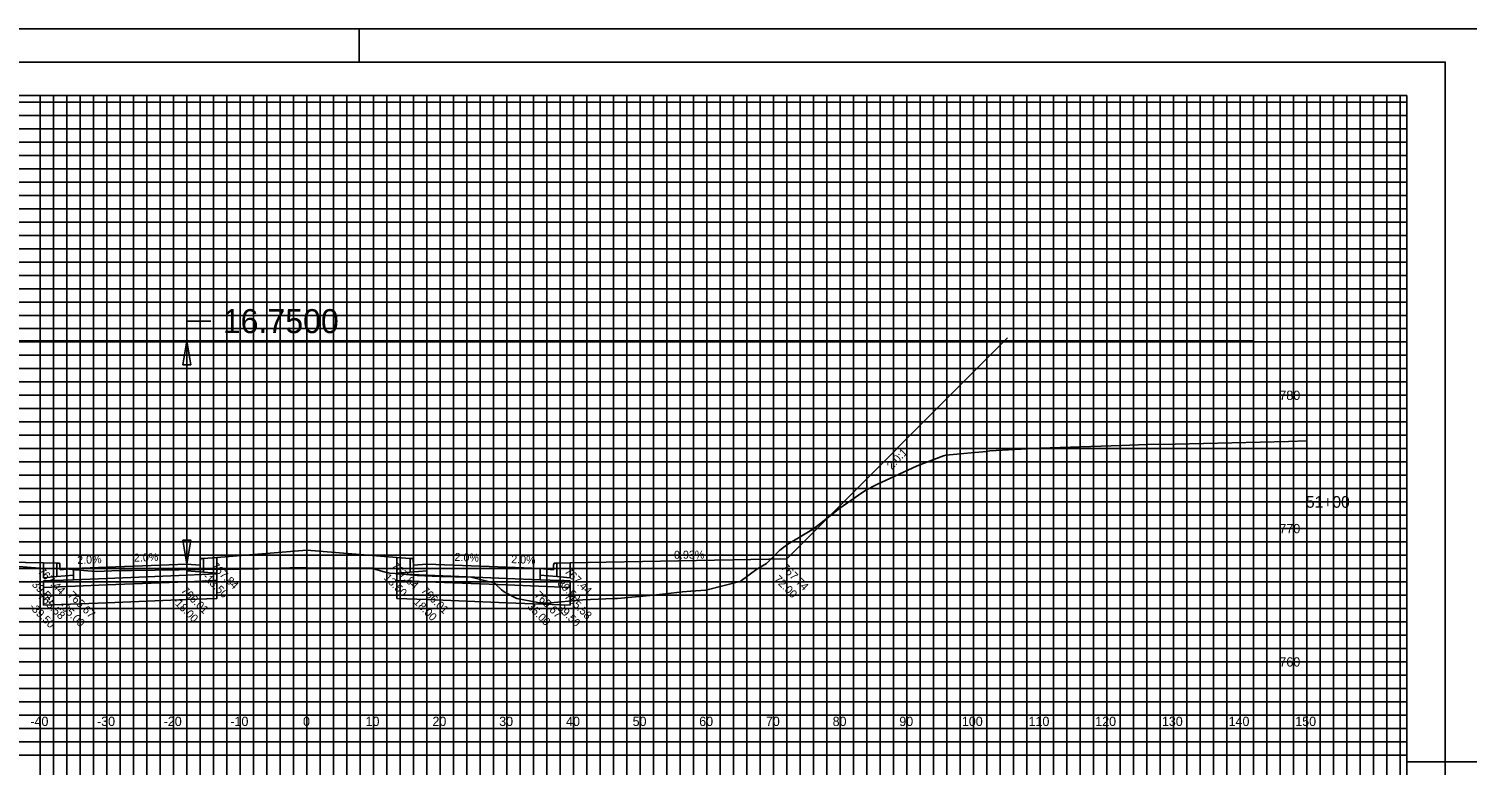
# Model space of a CAD drawing. Extents: x 578243 to 601557, y 174899 to 175559.
# Drawn here: x 600998.1 to 601213.9, y 175448.3 to 175558.8 of the extents above; entities that cross this region are included whole.
import ezdxf

# ---------------------------------------------------------------- set-up
doc = ezdxf.new("R2010")
doc.units = 0
for name, color, linetype in [('E_PROF_Grid', 7, 'Continuous'), ('E_PROF_GridMin', 7, 'Continuous'), ('P_CRDR_Label', 7, 'Continuous'), ('P_CRDR_Link', 7, 'Continuous'), ('P_E_XS_Ground', 7, 'Continuous'), ('P_RW_SlopeIntercepts', 7, 'Continuous'), ('P_XS_Text', 7, 'Continuous'), ('PLT_Sheet_Border', 7, 'Continuous'), ('PLT_Sheet_Info', 7, 'Continuous')]:
    doc.layers.add(name, color=color, linetype=linetype)

msp = doc.modelspace()

# ---------------------------------------------------------------- linework, layer by layer
at = {"layer": 'E_PROF_Grid'}
for p, q in [((600999.84, 175353.8), (600999.84, 175548.8)), ((601009.84, 175353.8), (601009.84, 175548.8)), ((601019.84, 175353.8), (601019.84, 175548.8)), ((601029.84, 175353.8), (601029.84, 175548.8)), ((601039.84, 175353.8), (601039.84, 175548.8)), ((601049.84, 175353.8), (601049.84, 175548.8)), ((601059.84, 175353.8), (601059.84, 175548.8)), ((601069.84, 175353.8), (601069.84, 175548.8)), ((601079.84, 175353.8), (601079.84, 175548.8)), ((601089.84, 175353.8), (601089.84, 175548.8)), ((601099.84, 175353.8), (601099.84, 175548.8)), ((601109.84, 175353.8), (601109.84, 175548.8)), ((601119.84, 175353.8), (601119.84, 175548.8)), ((601129.84, 175353.8), (601129.84, 175548.8)), ((601139.84, 175353.8), (601139.84, 175548.8)), ((601149.84, 175353.8), (601149.84, 175548.8)), ((601159.84, 175353.8), (601159.84, 175548.8)), ((601169.84, 175353.8), (601169.84, 175548.8)), ((601179.84, 175353.8), (601179.84, 175548.8)), ((601189.84, 175353.8), (601189.84, 175548.8)), ((601199.84, 175353.8), (601199.84, 175548.8)), ((600889.84, 175543.8), (601204.84, 175543.8)), ((600889.84, 175533.8), (601204.84, 175533.8)), ((600889.84, 175523.8), (601204.84, 175523.8)), ((600889.84, 175513.8), (601204.84, 175513.8)), ((600889.84, 175503.8), (601204.84, 175503.8)), ((600889.84, 175493.8), (601204.84, 175493.8)), ((600889.84, 175483.8), (601204.84, 175483.8)), ((600889.84, 175473.8), (601204.84, 175473.8)), ((600889.84, 175463.8), (601204.84, 175463.8)), ((600889.84, 175453.8), (601204.84, 175453.8))]:
    msp.add_line(p, q, dxfattribs=at)
at = {"layer": 'E_PROF_GridMin'}
for p, q in [((601001.84, 175353.8), (601001.84, 175548.8)), ((601003.84, 175353.8), (601003.84, 175548.8)), ((601005.84, 175353.8), (601005.84, 175548.8)), ((601007.84, 175353.8), (601007.84, 175548.8)), ((601011.84, 175353.8), (601011.84, 175548.8)), ((601013.84, 175353.8), (601013.84, 175548.8)), ((601015.84, 175353.8), (601015.84, 175548.8)), ((601017.84, 175353.8), (601017.84, 175548.8)), ((601021.84, 175353.8), (601021.84, 175548.8)), ((601023.84, 175353.8), (601023.84, 175548.8)), ((601025.84, 175353.8), (601025.84, 175548.8)), ((601027.84, 175353.8), (601027.84, 175548.8)), ((601031.84, 175353.8), (601031.84, 175548.8)), ((601033.84, 175353.8), (601033.84, 175548.8)), ((601035.84, 175353.8), (601035.84, 175548.8)), ((601037.84, 175353.8), (601037.84, 175548.8)), ((601041.84, 175353.8), (601041.84, 175548.8)), ((601043.84, 175353.8), (601043.84, 175548.8)), ((601045.84, 175353.8), (601045.84, 175548.8)), ((601047.84, 175353.8), (601047.84, 175548.8)), ((601051.84, 175353.8), (601051.84, 175548.8)), ((601053.84, 175353.8), (601053.84, 175548.8)), ((601055.84, 175353.8), (601055.84, 175548.8)), ((601057.84, 175353.8), (601057.84, 175548.8)), ((601061.84, 175353.8), (601061.84, 175548.8)), ((601063.84, 175353.8), (601063.84, 175548.8)), ((601065.84, 175353.8), (601065.84, 175548.8)), ((601067.84, 175353.8), (601067.84, 175548.8)), ((601071.84, 175353.8), (601071.84, 175548.8)), ((601073.84, 175353.8), (601073.84, 175548.8)), ((601075.84, 175353.8), (601075.84, 175548.8)), ((601077.84, 175353.8), (601077.84, 175548.8)), ((601081.84, 175353.8), (601081.84, 175548.8)), ((601083.84, 175353.8), (601083.84, 175548.8)), ((601085.84, 175353.8), (601085.84, 175548.8)), ((601087.84, 175353.8), (601087.84, 175548.8)), ((601091.84, 175353.8), (601091.84, 175548.8)), ((601093.84, 175353.8), (601093.84, 175548.8)), ((601095.84, 175353.8), (601095.84, 175548.8)), ((601097.84, 175353.8), (601097.84, 175548.8)), ((601101.84, 175353.8), (601101.84, 175548.8)), ((601103.84, 175353.8), (601103.84, 175548.8)), ((601105.84, 175353.8), (601105.84, 175548.8)), ((601107.84, 175353.8), (601107.84, 175548.8)), ((601111.84, 175353.8), (601111.84, 175548.8)), ((601113.84, 175353.8), (601113.84, 175548.8)), ((601115.84, 175353.8), (601115.84, 175548.8)), ((601117.84, 175353.8), (601117.84, 175548.8)), ((601121.84, 175353.8), (601121.84, 175548.8)), ((601123.84, 175353.8), (601123.84, 175548.8)), ((601125.84, 175353.8), (601125.84, 175548.8)), ((601127.84, 175353.8), (601127.84, 175548.8)), ((601131.84, 175353.8), (601131.84, 175548.8)), ((601133.84, 175353.8), (601133.84, 175548.8)), ((601135.84, 175353.8), (601135.84, 175548.8)), ((601137.84, 175353.8), (601137.84, 175548.8)), ((601141.84, 175353.8), (601141.84, 175548.8)), ((601143.84, 175353.8), (601143.84, 175548.8)), ((601145.84, 175353.8), (601145.84, 175548.8)), ((601147.84, 175353.8), (601147.84, 175548.8)), ((601151.84, 175353.8), (601151.84, 175548.8)), ((601153.84, 175353.8), (601153.84, 175548.8)), ((601155.84, 175353.8), (601155.84, 175548.8)), ((601157.84, 175353.8), (601157.84, 175548.8)), ((601161.84, 175353.8), (601161.84, 175548.8)), ((601163.84, 175353.8), (601163.84, 175548.8)), ((601165.84, 175353.8), (601165.84, 175548.8)), ((601167.84, 175353.8), (601167.84, 175548.8)), ((601171.84, 175353.8), (601171.84, 175548.8)), ((601173.84, 175353.8), (601173.84, 175548.8)), ((601175.84, 175353.8), (601175.84, 175548.8)), ((601177.84, 175353.8), (601177.84, 175548.8)), ((601181.84, 175353.8), (601181.84, 175548.8)), ((601183.84, 175353.8), (601183.84, 175548.8)), ((601185.84, 175353.8), (601185.84, 175548.8)), ((601187.84, 175353.8), (601187.84, 175548.8)), ((601191.84, 175353.8), (601191.84, 175548.8)), ((601193.84, 175353.8), (601193.84, 175548.8)), ((601195.84, 175353.8), (601195.84, 175548.8)), ((601197.84, 175353.8), (601197.84, 175548.8)), ((601201.84, 175353.8), (601201.84, 175548.8)), ((601203.84, 175353.8), (601203.84, 175548.8)), ((600889.84, 175547.8), (601204.84, 175547.8)), ((600889.84, 175545.8), (601204.84, 175545.8)), ((600889.84, 175541.8), (601204.84, 175541.8)), ((600889.84, 175539.8), (601204.84, 175539.8)), ((600889.84, 175537.8), (601204.84, 175537.8)), ((600889.84, 175535.8), (601204.84, 175535.8)), ((600889.84, 175531.8), (601204.84, 175531.8)), ((600889.84, 175529.8), (601204.84, 175529.8)), ((600889.84, 175527.8), (601204.84, 175527.8)), ((600889.84, 175525.8), (601204.84, 175525.8)), ((600889.84, 175521.8), (601204.84, 175521.8)), ((600889.84, 175519.8), (601204.84, 175519.8)), ((600889.84, 175517.8), (601204.84, 175517.8)), ((600889.84, 175515.8), (601204.84, 175515.8)), ((600889.84, 175511.8), (601204.84, 175511.8)), ((600889.84, 175509.8), (601204.84, 175509.8)), ((600889.84, 175507.8), (601204.84, 175507.8)), ((600889.84, 175505.8), (601204.84, 175505.8)), ((600889.84, 175501.8), (601204.84, 175501.8)), ((600889.84, 175499.8), (601204.84, 175499.8)), ((600889.84, 175497.8), (601204.84, 175497.8)), ((600889.84, 175495.8), (601204.84, 175495.8)), ((600889.84, 175491.8), (601204.84, 175491.8)), ((600889.84, 175489.8), (601204.84, 175489.8)), ((600889.84, 175487.8), (601204.84, 175487.8)), ((600889.84, 175485.8), (601204.84, 175485.8)), ((600889.84, 175481.8), (601204.84, 175481.8)), ((600889.84, 175479.8), (601204.84, 175479.8)), ((600889.84, 175477.8), (601204.84, 175477.8)), ((600889.84, 175475.8), (601204.84, 175475.8)), ((600889.84, 175471.8), (601204.84, 175471.8)), ((600889.84, 175469.8), (601204.84, 175469.8)), ((600889.84, 175467.8), (601204.84, 175467.8)), ((600889.84, 175465.8), (601204.84, 175465.8)), ((600889.84, 175461.8), (601204.84, 175461.8)), ((600889.84, 175459.8), (601204.84, 175459.8)), ((600889.84, 175457.8), (601204.84, 175457.8)), ((600889.84, 175455.8), (601204.84, 175455.8)), ((600889.84, 175451.8), (601204.84, 175451.8)), ((600889.84, 175449.8), (601204.84, 175449.8))]:
    msp.add_line(p, q, dxfattribs=at)
at = {"layer": 'P_CRDR_Link'}
msp.add_line((601144.95, 175512.4), (601111.84, 175479.28), dxfattribs=at)
for points in [[(601026.34, 175479.48), (601039.84, 175480.56)], [(601026.34, 175479.48), (601039.84, 175480.56)], [(601039.84, 175480.56), (601026.34, 175479.48)], [(601039.84, 175480.56), (601053.34, 175479.48)], [(601039.84, 175480.56), (601053.34, 175479.48)], [(601053.34, 175479.48), (601039.84, 175480.56)], [(601000.34, 175478.68), (600967.84, 175479.28)], [(601000.34, 175478.68), (600967.84, 175479.28)], [(601002.34, 175478.64), (601000.34, 175478.68)], [(601000.34, 175478.68), (601000.34, 175476.44)], [(601000.34, 175478.68), (601000.34, 175476.44)], [(601000.34, 175478.68), (601000.34, 175476.44)], [(601002.66, 175478.64), (601002.34, 175478.64)], [(601002.66, 175478.64), (601002.34, 175478.64)], [(601002.34, 175478.64), (601002.34, 175476.6)], [(601002.34, 175476.6), (601002.34, 175478.64)], [(601002.74, 175478.6), (601002.66, 175478.64)], [(601002.74, 175478.6), (601002.66, 175478.64)], [(601002.8, 175478.48), (601002.74, 175478.6)], [(601002.8, 175478.48), (601002.74, 175478.6)], [(601002.82, 175478.32), (601002.8, 175478.48)], [(601002.82, 175478.32), (601002.8, 175478.48)], [(601002.84, 175477.64), (601002.82, 175478.32)], [(601002.84, 175477.64), (601002.82, 175478.32)], [(601004.84, 175477.8), (601002.84, 175477.64)], [(601004.84, 175477.8), (601002.84, 175477.64)], [(601009.84, 175478), (601004.84, 175477.8)], [(601004.84, 175477.8), (601004.84, 175476.14)], [(601004.84, 175476.8), (601004.84, 175477.8)], [(601021.84, 175478.48), (601009.84, 175478)], [(601009.84, 175478), (601009.84, 175476.34)], [(601009.84, 175478), (601009.84, 175476.34)], [(601021.84, 175478.48), (601021.84, 175476.82)], [(601021.84, 175478.48), (601021.84, 175476.82)], [(601021.84, 175478.48), (601021.84, 175476.82)], [(601021.84, 175478.48), (601023.84, 175478.32)], [(601021.84, 175478.48), (601023.84, 175478.32)], [(601021.84, 175477.48), (601021.84, 175478.48)], [(601024.34, 175477.28), (601021.84, 175477.48)], [(601024.34, 175477.28), (601021.84, 175477.48)], [(601023.84, 175478.32), (601023.85, 175479)], [(601023.84, 175478.32), (601023.85, 175479)], [(601023.85, 175479), (601023.88, 175479.16)], [(601023.85, 175479), (601023.88, 175479.16)], [(601023.88, 175479.16), (601023.94, 175479.28)], [(601023.88, 175479.16), (601023.94, 175479.28)], [(601023.94, 175479.28), (601024.02, 175479.32)], [(601023.94, 175479.28), (601024.02, 175479.32)], [(601024.02, 175479.32), (601024.34, 175479.32)], [(601024.02, 175479.32), (601024.34, 175479.32)], [(601024.34, 175479.32), (601026.34, 175479.48)], [(601024.34, 175479.32), (601024.34, 175477.28)], [(601024.34, 175477.28), (601024.34, 175479.32)], [(601026.34, 175479.48), (601026.34, 175477.12)], [(601026.34, 175479.48), (601026.34, 175477.12)], [(601026.34, 175479.48), (601026.34, 175477.12)], [(601026.34, 175479.48), (601026.34, 175479.48)], [(601026.34, 175479.48), (601026.34, 175479.48)], [(601026.34, 175479.48), (601026.34, 175479.48)], [(601055.34, 175479.32), (601053.34, 175479.48)], [(601053.34, 175479.48), (601053.34, 175477.12)], [(601053.34, 175479.48), (601053.34, 175477.12)], [(601053.34, 175479.48), (601053.34, 175477.12)], [(601053.34, 175479.48), (601053.34, 175479.48)], [(601053.34, 175479.48), (601053.34, 175479.48)], [(601053.34, 175479.48), (601053.34, 175479.48)], [(601055.66, 175479.32), (601055.34, 175479.32)], [(601055.66, 175479.32), (601055.34, 175479.32)], [(601055.34, 175479.32), (601055.34, 175477.28)], [(601055.34, 175477.28), (601055.34, 175479.32)], [(601055.34, 175477.28), (601057.84, 175477.48)], [(601055.34, 175477.28), (601057.84, 175477.48)], [(601055.74, 175479.28), (601055.66, 175479.32)], [(601055.74, 175479.28), (601055.66, 175479.32)], [(601055.8, 175479.16), (601055.74, 175479.28)], [(601055.8, 175479.16), (601055.74, 175479.28)], [(601055.82, 175479), (601055.8, 175479.16)], [(601055.82, 175479), (601055.8, 175479.16)], [(601055.84, 175478.32), (601055.82, 175479)], [(601055.84, 175478.32), (601055.82, 175479)], [(601057.84, 175478.48), (601055.84, 175478.32)], [(601057.84, 175478.48), (601055.84, 175478.32)], [(601057.84, 175478.48), (601069.84, 175478)], [(601057.84, 175478.48), (601057.84, 175476.82)], [(601057.84, 175478.48), (601057.84, 175476.82)], [(601057.84, 175478.48), (601057.84, 175476.82)], [(601057.84, 175477.48), (601057.84, 175478.48)], [(601069.84, 175478), (601069.84, 175476.34)], [(601069.84, 175478), (601074.84, 175477.8)], [(601069.84, 175478), (601069.84, 175476.34)], [(601074.84, 175477.8), (601074.84, 175476.14)], [(601074.84, 175477.8), (601076.84, 175477.64)], [(601074.84, 175477.8), (601076.84, 175477.64)], [(601074.84, 175476.8), (601074.84, 175477.8)], [(601076.84, 175477.64), (601076.85, 175478.32)], [(601076.84, 175477.64), (601076.85, 175478.32)], [(601076.85, 175478.32), (601076.88, 175478.48)], [(601076.85, 175478.32), (601076.88, 175478.48)], [(601076.88, 175478.48), (601076.94, 175478.6)], [(601076.88, 175478.48), (601076.94, 175478.6)], [(601076.94, 175478.6), (601077.02, 175478.64)], [(601076.94, 175478.6), (601077.02, 175478.64)], [(601077.02, 175478.64), (601077.34, 175478.64)], [(601077.02, 175478.64), (601077.34, 175478.64)], [(601077.34, 175478.64), (601079.34, 175478.68)], [(601077.34, 175478.64), (601077.34, 175476.6)], [(601077.34, 175476.6), (601077.34, 175478.64)], [(601079.34, 175478.68), (601111.84, 175479.28)], [(601079.34, 175478.68), (601111.84, 175479.28)], [(601079.34, 175478.68), (601079.34, 175476.44)], [(601079.34, 175478.68), (601079.34, 175476.44)], [(601079.34, 175478.68), (601079.34, 175476.44)], [(601000.34, 175476.44), (601002.34, 175476.6)], [(601004.84, 175476.14), (601000.34, 175475.96)], [(601000.34, 175475.96), (601000.34, 175474.96)], [(601009.84, 175475.34), (601000.34, 175474.96)], [(601002.34, 175476.6), (601004.84, 175476.8)], [(601002.34, 175476.6), (601004.84, 175476.8)], [(601009.84, 175476.34), (601004.84, 175476.14)], [(601021.84, 175476.82), (601009.84, 175476.34)], [(601009.84, 175476.34), (601009.84, 175475.34)], [(601009.84, 175476.34), (601009.84, 175475.34)], [(601021.84, 175475.82), (601009.84, 175475.34)], [(601009.84, 175475.34), (601009.84, 175472.67)], [(601009.84, 175475.34), (601009.84, 175472.67)], [(601026.34, 175477), (601021.84, 175476.82)], [(601021.84, 175476.82), (601021.84, 175475.82)], [(601021.84, 175476.82), (601021.84, 175475.82)], [(601021.84, 175476.82), (601021.84, 175475.82)], [(601026.34, 175476), (601021.84, 175475.82)], [(601021.84, 175475.82), (601021.84, 175473.15)], [(601021.84, 175475.82), (601021.84, 175473.15)], [(601021.84, 175475.82), (601021.84, 175473.15)], [(601026.34, 175477.12), (601024.34, 175477.28)], [(601026.34, 175477), (601026.34, 175476)], [(601026.34, 175476), (601026.34, 175473.33)], [(601053.34, 175477.12), (601055.34, 175477.28)], [(601053.34, 175477), (601057.84, 175476.82)], [(601053.34, 175477), (601053.34, 175476)], [(601053.34, 175476), (601057.84, 175475.82)], [(601053.34, 175476), (601053.34, 175473.33)], [(601057.84, 175476.82), (601069.84, 175476.34)], [(601057.84, 175476.82), (601057.84, 175475.82)], [(601057.84, 175476.82), (601057.84, 175475.82)], [(601057.84, 175476.82), (601057.84, 175475.82)], [(601057.84, 175475.82), (601069.84, 175475.34)], [(601057.84, 175475.82), (601057.84, 175473.15)], [(601057.84, 175475.82), (601057.84, 175473.15)], [(601057.84, 175475.82), (601057.84, 175473.15)], [(601069.84, 175476.34), (601069.84, 175475.34)], [(601069.84, 175476.34), (601074.84, 175476.14)], [(601069.84, 175476.34), (601069.84, 175475.34)], [(601069.84, 175475.34), (601069.84, 175472.67)], [(601069.84, 175475.34), (601079.34, 175474.96)], [(601069.84, 175475.34), (601069.84, 175472.67)], [(601077.34, 175476.6), (601074.84, 175476.8)], [(601077.34, 175476.6), (601074.84, 175476.8)], [(601074.84, 175476.14), (601079.34, 175475.96)], [(601079.34, 175476.44), (601077.34, 175476.6)], [(601079.34, 175475.96), (601079.34, 175474.96)], [(601000.34, 175474.96), (601000.34, 175472.29)], [(601021.84, 175473.15), (601009.84, 175472.67)], [(601021.84, 175473.15), (601026.34, 175473.33)], [(601057.84, 175473.15), (601053.34, 175473.33)], [(601057.84, 175473.15), (601069.84, 175472.67)], [(601079.34, 175474.96), (601079.34, 175472.29)], [(601009.84, 175472.67), (601000.34, 175472.29)], [(601069.84, 175472.67), (601079.34, 175472.29)]]:
    msp.add_lwpolyline(points, dxfattribs=at)
at = {"layer": 'P_E_XS_Ground'}
msp.add_lwpolyline([(600996.63, 175478.11), (601000.4, 175477.81), (601001.9, 175477.83), (601003.72, 175477.76), (601005.09, 175477.64), (601008.31, 175477.35), (601010.62, 175477.48), (601011.99, 175477.5), (601013.55, 175477.51), (601024.24, 175477.65), (601029.93, 175477.74), (601032.63, 175477.76), (601037.31, 175477.94), (601039.84, 175477.93), (601047.55, 175477.87), (601049.69, 175477.85), (601050.19, 175477.69), (601051.44, 175477.34), (601052.29, 175477.12), (601053.09, 175477.09), (601056.39, 175476.76), (601059.78, 175476.62), (601064.48, 175476.52), (601067.25, 175475.8), (601067.81, 175475.7), (601068.13, 175475.44), (601069.07, 175474.62), (601069.59, 175474.23), (601071.37, 175473.29), (601074.5, 175472.7), (601075.2, 175472.62), (601075.89, 175472.6), (601081.23, 175473.12), (601084.67, 175473.26), (601085.87, 175473.29), (601086.42, 175473.29), (601091.83, 175473.83), (601093.63, 175474.03), (601096.19, 175474.32), (601097.42, 175474.42), (601099.68, 175474.58), (601099.91, 175474.63), (601099.91, 175474.63), (601104.8, 175475.85), (601104.84, 175475.86), (601107.33, 175477.74), (601108.78, 175478.59), (601110.77, 175480.59), (601112, 175481.49), (601112.86, 175481.95), (601115.84, 175483.79), (601117.88, 175485.36), (601119.79, 175486.87), (601122.6, 175488.83), (601123.69, 175489.57), (601125.36, 175490.43), (601131.37, 175493.24), (601135.35, 175494.71), (601135.67, 175494.8), (601140.03, 175495.23), (601141.83, 175495.38), (601142.31, 175495.46), (601149.79, 175495.89), (601162.04, 175496.29), (601165.86, 175496.4), (601170.07, 175496.47), (601187.07, 175496.87), (601189.84, 175496.96)], dxfattribs=at)
at = {"layer": 'P_RW_SlopeIntercepts'}
for p, q in [((601021.84, 175514.91), (601025.44, 175514.91)), ((601021.84, 175478.48), (601021.84, 175514.91)), ((600921.84, 175511.98), (601181.84, 175511.98))]:
    msp.add_line(p, q, dxfattribs=at)
for points in [[(601021.24, 175508.38), (601022.44, 175508.38), (601021.84, 175511.98)], [(601021.24, 175482.08), (601022.44, 175482.08), (601021.84, 175478.48)]]:
    msp.add_lwpolyline(points, close=True, dxfattribs=at)
at = {"layer": 'PLT_Sheet_Border'}
for points in [[(600877.19, 175338.8), (601217.19, 175338.8), (601217.19, 175558.8), (600877.19, 175558.8)], [(600879.59, 175343.8), (601210.59, 175343.8), (601210.59, 175553.8), (600879.59, 175553.8)]]:
    msp.add_lwpolyline(points, close=True, dxfattribs=at)
at = {"layer": 'PLT_Sheet_Info'}
for p, q in [((601042.69, 175558.8), (601052.69, 175558.8)), ((601047.69, 175558.8), (601047.69, 175553.8)), ((601207.19, 175558.8), (601217.19, 175558.8)), ((600889.84, 175548.8), (601204.84, 175548.8)), ((601204.84, 175348.8), (601204.84, 175548.8)), ((601217.19, 175448.8), (601204.84, 175448.8))]:
    msp.add_line(p, q, dxfattribs=at)

# ---------------------------------------------------------------- texts
at = {"layer": 'P_CRDR_Label'}
for s, rotation, p in [('2.0:1', 46.711, (601127.58, 175492.57)), ('2.0%', 2.2906, (601005.43, 175478.48)), ('2.0%', 2.2906, (601013.93, 175478.82)), ('2.0%', 357.7094, (601061.98, 175478.97)), ('2.0%', 357.7094, (601070.48, 175478.63)), ('0.93%', 0.4313, (601094.93, 175479.27)), ('767.44', 315, (600999.41, 175477.27)), ('767.84', 315, (601025.41, 175478.07)), ('767.84', 315, (601052.41, 175478.07)), ('767.44', 315, (601078.41, 175477.27)), ('767.74', 315, (601110.91, 175477.87)), ('-39.50', 315, (600998.14, 175475.7)), ('766.01', 315, (601020.91, 175474.4)), ('766.01', 315, (601020.91, 175474.4)), ('766.01', 315, (601020.91, 175474.4)), ('-13.50', 315, (601024.14, 175476.5)), ('13.50', 315, (601051.31, 175476.33)), ('766.01', 315, (601056.91, 175474.4)), ('766.01', 315, (601056.91, 175474.4)), ('766.01', 315, (601056.91, 175474.4)), ('39.50', 315, (601077.33, 175475.5)), ('72.00', 315, (601109.83, 175476.11)), ('765.58', 315, (600999.41, 175473.54)), ('765.67', 315, (601003.91, 175473.72)), ('-18.00', 315, (601019.62, 175472.85)), ('-18.00', 315, (601019.62, 175472.85)), ('-18.00', 315, (601019.62, 175472.85)), ('18.00', 315, (601055.79, 175472.68)), ('18.00', 315, (601055.79, 175472.68)), ('18.00', 315, (601055.79, 175472.68)), ('765.67', 315, (601073.91, 175473.72)), ('765.58', 315, (601078.41, 175473.54)), ('-39.50', 315, (600998.13, 175471.98)), ('-35.00', 315, (601002.63, 175472.16)), ('35.00', 315, (601072.82, 175471.97)), ('39.50', 315, (601077.32, 175471.79))]:
    msp.add_text(s, height=1.2, rotation=rotation, dxfattribs=at).set_placement(p)
at = {"layer": 'P_RW_SlopeIntercepts'}
msp.add_text('16.7500', height=3.6, dxfattribs=at).set_placement((601027.24, 175513.13))
at = {"layer": 'P_XS_Text'}
for s, height, p in [('780', 1.4, (601185.72, 175503.1)), ('51+00', 1.75, (601189.7, 175486.93)), ('770', 1.4, (601185.72, 175483.1)), ('760', 1.4, (601185.72, 175463.1)), ('-40', 1.4, (600998.38, 175454.18)), ('-30', 1.4, (601008.38, 175454.18)), ('-20', 1.4, (601018.38, 175454.18)), ('-10', 1.4, (601028.38, 175454.18)), ('0', 1.4, (601039.28, 175454.18)), ('0', 1.4, (601039.28, 175454.18)), ('10', 1.4, (601048.66, 175454.18)), ('20', 1.4, (601058.69, 175454.18)), ('30', 1.4, (601068.7, 175454.18)), ('40', 1.4, (601078.73, 175454.18)), ('50', 1.4, (601088.71, 175454.18)), ('60', 1.4, (601098.7, 175454.18)), ('70', 1.4, (601108.7, 175454.18)), ('80', 1.4, (601118.71, 175454.18)), ('90', 1.4, (601128.71, 175454.18)), ('100', 1.4, (601138.1, 175454.18)), ('110', 1.4, (601148.1, 175454.18)), ('120', 1.4, (601158.1, 175454.18)), ('130', 1.4, (601168.1, 175454.18)), ('140', 1.4, (601178.1, 175454.18)), ('150', 1.4, (601188.1, 175454.18))]:
    msp.add_text(s, height=height, rotation=360, dxfattribs=at).set_placement(p)

doc.saveas('drawing.dxf')
